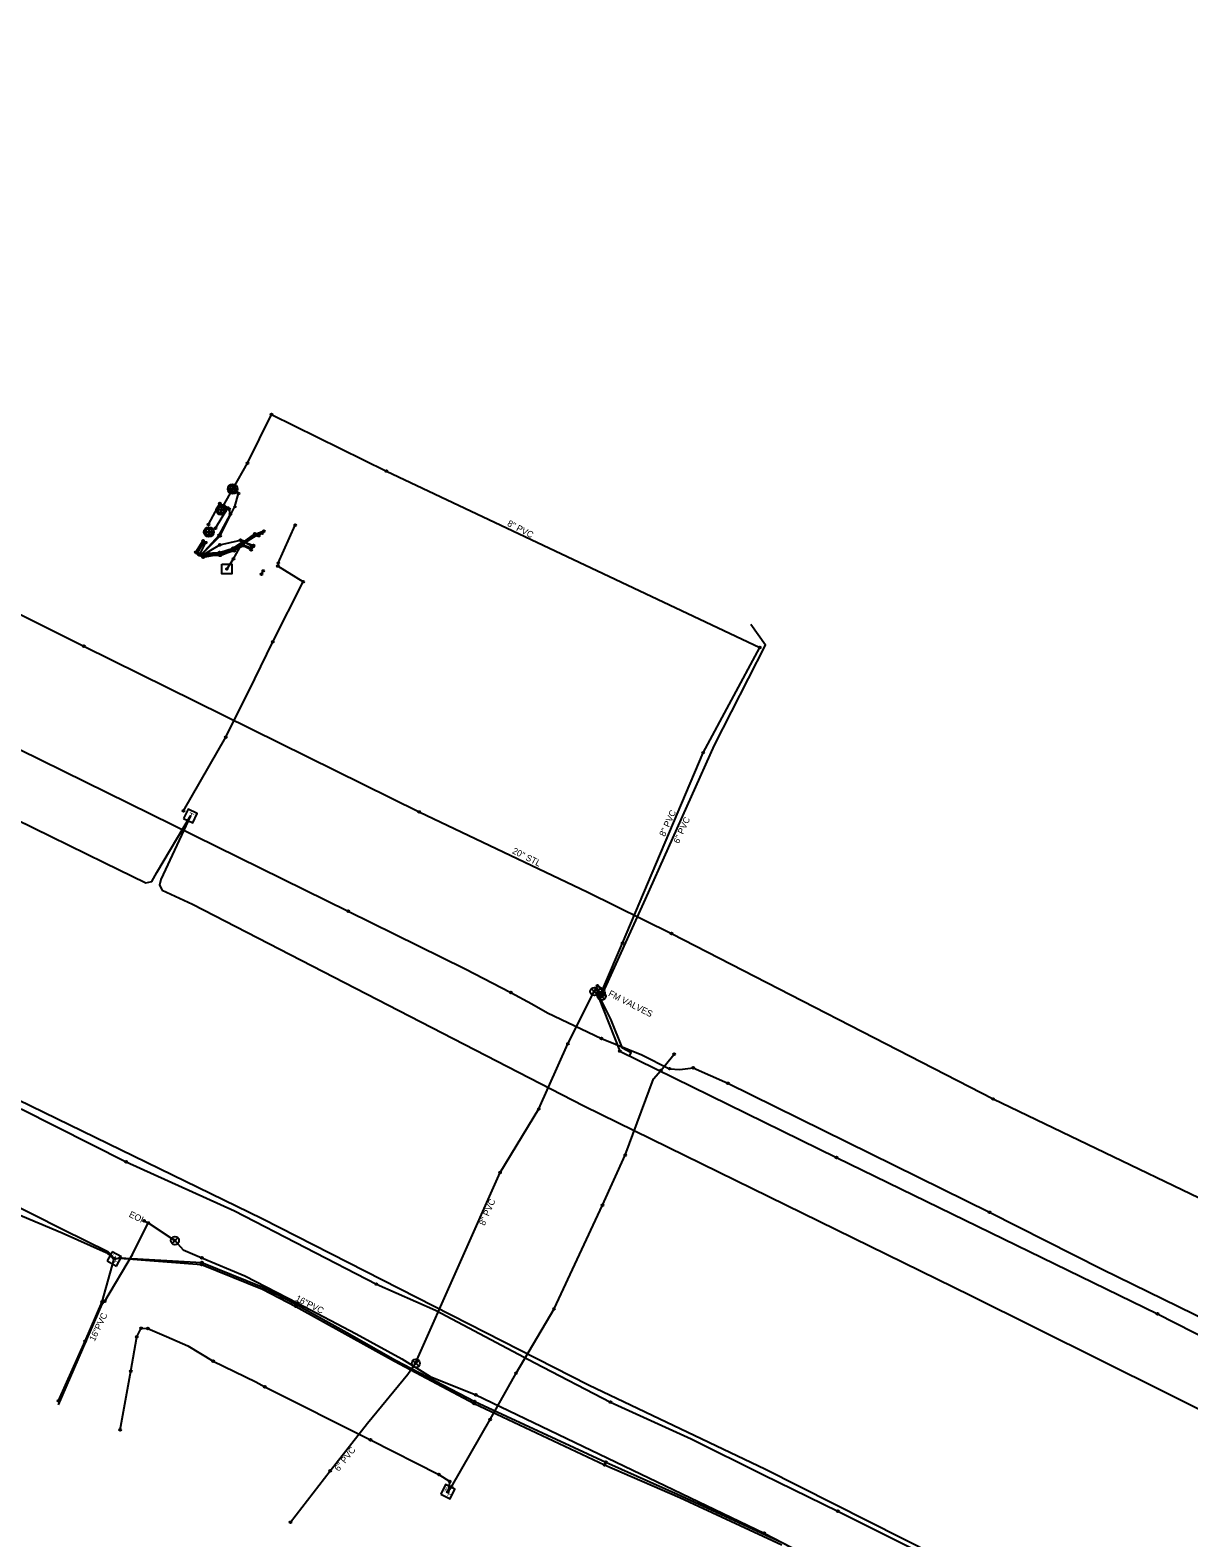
# Model space of a CAD drawing. Extents: x 2244485 to 2250986, y 199568 to 203007.
# Drawn here: x 2245302 to 2245934, y 202136 to 202958 of the extents above; entities that cross this region are included whole.
import ezdxf

# ---------------------------------------------------------------- set-up
doc = ezdxf.new("R2010")
doc.units = 0
for name, color, linetype in [('Default', 7, 'Continuous'), ('Exist Utilities Gas UG Line SUE LOS B', 7, 'Continuous'), ('Exist Utilities Gas UG Line SUE LOS B Text', 7, 'Continuous'), ('Exist Utilities Other Pole With Base CELL', 7, 'Continuous'), ('Exist Utilities Power UG Cable SUE LOS B', 7, 'Continuous'), ('Exist Utilities Sanitary Sewer Forced Main SUE LOS B', 7, 'Continuous'), ('Exist Utilities Sanitary Sewer Forced Main SUE LOS B Text', 7, 'Continuous'), ('Exist Utilities Sanitary Sewer Forced Main SUE LOS C', 7, 'Continuous'), ('Exist Utilities Sanitary Sewer Manhole CELL', 7, 'Continuous'), ('Exist Utilities Telephone Hand Hole CELL', 7, 'Continuous'), ('Exist Utilities Telephone Pedestal CELL', 7, 'Continuous'), ('Exist Utilities Telephone UG Cable SUE LOS C', 7, 'Continuous'), ('Exist Utilities Telephone UG FO SUE LOS B', 7, 'Continuous'), ('Exist Utilities Telephone UG FO SUE LOS C', 7, 'Continuous'), ('Exist Utilities TV Hand Hole CELL', 7, 'Continuous'), ('Exist Utilities TV UG FO Cable SUE LOS B', 7, 'Continuous'), ('Exist Utilities Water UG Line SUE LOS B', 7, 'Continuous'), ('Exist Utilities Water UG Line SUE LOS B Text', 7, 'Continuous'), ('Exist Utilities Water Valve CELL', 7, 'Continuous')]:
    doc.layers.add(name, color=color, linetype=linetype)

# ---------------------------------------------------------------- blocks, each defined once
blk = doc.blocks.new('SurveyPointCell')
at = {"layer": 'Default'}
for p, q in [((-0.5, 0), (0.5, 0)), ((0, -0.5), (0, 0.5))]:
    blk.add_line(p, q, dxfattribs=at)
blk.add_circle((0, 0), 0.5, dxfattribs=at)

msp = doc.modelspace()

# ---------------------------------------------------------------- linework, layer by layer
at = {"layer": 'Exist Utilities Gas UG Line SUE LOS B'}
msp.add_lwpolyline([(2244658.96, 202958.49), (2244721.96, 202928.3), (2244863.47, 202856.19), (2244912.51, 202831.57), (2245070.07, 202752.33), (2245256.14, 202659.91), (2245331.4, 202622.29), (2245514.38, 202531.76), (2245606.53, 202488.05), (2245652.12, 202465.42), (2245827.69, 202375.08), (2246001.01, 202291.84), (2246162.3, 202211.17), (2246329.12, 202125.74), (2246513.99, 202036.93), (2246642.7, 201974.75), (2246734.96, 201930.33), (2246858.92, 201868.26), (2246999.42, 201799.12), (2247177.53, 201710.71), (2247331.7, 201633.3), (2247466.92, 201567.22), (2247602.4, 201501.88), (2247749.1, 201426.01)], dxfattribs=at)
at = {"layer": 'Exist Utilities Other Pole With Base CELL'}
msp.add_line((2245409.46, 202664.37), (2245409.46, 202664.37), dxfattribs=at)
msp.add_lwpolyline([(2245406.73, 202667.07), (2245412.13, 202667.07), (2245412.13, 202661.67), (2245406.73, 202661.67), (2245406.73, 202667.07)], dxfattribs=at)
msp.add_circle((2245409.46, 202664.37), 0.0707, dxfattribs=at)
at = {"layer": 'Exist Utilities Power UG Cable SUE LOS B'}
for points in [[(2245395.21, 202671.86), (2245405.81, 202682.51), (2245413.9, 202698.4), (2245415.78, 202705.61)], [(2245395.33, 202671.83), (2245405.27, 202682.8), (2245411.37, 202694.33), (2245410.76, 202697.01)], [(2245437.55, 202667.62), (2245446.8, 202688.25)], [(2245392.56, 202673.48), (2245396.48, 202679.84)], [(2245396.95, 202679.11), (2245393.18, 202673.08)], [(2245393.77, 202672.75), (2245405.4, 202673.36), (2245412.94, 202675.71), (2245418.44, 202679.4), (2245424.01, 202677.24)], [(2245395.73, 202671.77), (2245405.63, 202677.57), (2245416.92, 202680.14), (2245423.82, 202676.57)], [(2245429.7, 202685.08), (2245424.88, 202683.28), (2245417.62, 202677.84), (2245413.1, 202675.46), (2245405.7, 202672.79), (2245396.4, 202671.15)], [(2245396.56, 202670.79), (2245405.7, 202672.45), (2245412.88, 202675.03), (2245417.7, 202677.69), (2245425.38, 202682.74), (2245428.75, 202683.95)], [(2245409.51, 202664.36), (2245413.06, 202669.87), (2245418, 202678.73), (2245424.77, 202683.65), (2245426.85, 202682.55)], [(2245422.72, 202674.83), (2245418.33, 202677.06), (2245413.53, 202674.26), (2245405.87, 202671.92), (2245394.27, 202672.11)], [(2245394.73, 202672.37), (2245397.93, 202678.77)], [(2245395.22, 202671.88), (2245405.74, 202671.81), (2245413.6, 202674.81), (2245418.32, 202677.62), (2245422.7, 202675.95)], [(2245385.83, 202532.39), (2245408.84, 202572.53), (2245424.65, 202604.36), (2245434.48, 202624.66), (2245451.18, 202657.41), (2245437.28, 202665.96)], [(2245428.32, 202661.55), (2245429.35, 202663.31)]]:
    msp.add_lwpolyline(points, dxfattribs=at)
at = {"layer": 'Exist Utilities Sanitary Sewer Forced Main SUE LOS B'}
for points in [[(2245399.42, 202688.67), (2245405.58, 202700.11), (2245407.65, 202699.04), (2245412.89, 202708.23), (2245420.72, 202722.07), (2245433.83, 202748.71), (2245496.51, 202717.84), (2245700.29, 202621.51)], [(2245403.32, 202686.64), (2245409.93, 202697.68), (2245407.63, 202698.99)], [(2245613.42, 202432.81), (2245614.64, 202435.08), (2245625.46, 202460.2), (2245669.41, 202564.11), (2245700.29, 202621.51)], [(2245512.48, 202230.83), (2245558.55, 202334.95), (2245579.66, 202369.62), (2245595.61, 202405.24), (2245610, 202433.72), (2245611.68, 202436.87), (2245614.64, 202435.08)], [(2245613.42, 202432.81), (2245612.33, 202430.62), (2245623.88, 202401.25), (2245742.14, 202343.1), (2245917.37, 202257.79), (2246026.41, 202202.34), (2246210.46, 202111.93), (2246345.24, 202046.28), (2246501.59, 201967.74), (2246585.87, 201926.12), (2246766.44, 201836.2), (2246874.3, 201784.12), (2246993.56, 201724.08), (2247186.6, 201626.85), (2247291.7, 201574.36), (2247419.93, 201509.91), (2247528.38, 201455.85), (2247631.36, 201405.97), (2247735.41, 201350.67), (2247801.59, 201317.51)], [(2245444.17, 202144.04), (2245465.88, 202172.11), (2245486.13, 202198.15), (2245508.27, 202224.8), (2245512.48, 202230.83)]]:
    msp.add_lwpolyline(points, dxfattribs=at)
at = {"layer": 'Exist Utilities Sanitary Sewer Forced Main SUE LOS C'}
msp.add_lwpolyline([(2245629.15, 202398.66), (2245630.09, 202400.26), (2245625.31, 202402.84), (2245619.07, 202418.57), (2245613.43, 202429.99), (2245613.98, 202431.19), (2245637.91, 202484.15), (2245675.61, 202568.28), (2245703.37, 202622.81), (2245695.34, 202634.02)], dxfattribs=at)
at = {"layer": 'Exist Utilities Sanitary Sewer Manhole CELL'}
for points in [[(2245412.59, 202709.74), (2245412.59, 202706.32), (2245412.59, 202708.03), (2245414.31, 202708.03), (2245410.88, 202708.03)], [(2245406.35, 202698.31), (2245406.35, 202694.88), (2245406.35, 202696.6), (2245408.06, 202696.6), (2245404.63, 202696.6)], [(2245399.64, 202686.24), (2245399.64, 202682.82), (2245399.64, 202684.53), (2245401.35, 202684.53), (2245397.93, 202684.53)]]:
    msp.add_lwpolyline(points, dxfattribs=at)
for centre, radius in [((2245412.59, 202708.03), 2.69), ((2245412.59, 202708.03), 1.71), ((2245406.35, 202696.6), 2.69), ((2245406.35, 202696.6), 1.71), ((2245399.64, 202684.53), 2.69), ((2245399.64, 202684.53), 1.71)]:
    msp.add_circle(centre, radius, dxfattribs=at)
at = {"layer": 'Exist Utilities Telephone Hand Hole CELL'}
for p, q in [((2245346.95, 202291.69), (2245344.18, 202286.68)), ((2245344.18, 202286.68), (2245349.19, 202283.91)), ((2245351.96, 202288.92), (2245346.95, 202291.69)), ((2245348.07, 202287.8), (2245348.07, 202287.8)), ((2245349.19, 202283.91), (2245351.96, 202288.92))]:
    msp.add_line(p, q, dxfattribs=at)
at = {"layer": 'Exist Utilities Telephone Pedestal CELL'}
msp.add_line((2245389.55, 202529.63), (2245389.55, 202529.63), dxfattribs=at)
msp.add_lwpolyline([(2245385.88, 202528.23), (2245390.95, 202525.86), (2245393.32, 202530.92), (2245388.26, 202533.3), (2245385.88, 202528.23)], dxfattribs=at)
at = {"layer": 'Exist Utilities Telephone UG Cable SUE LOS C'}
msp.add_lwpolyline([(2245130.24, 202608.24), (2245342.53, 202504.23), (2245365.2, 202493.05), (2245368.49, 202493.82), (2245371.26, 202498.68), (2245389.55, 202529.63), (2245373.43, 202494.83), (2245372.62, 202491.73), (2245374.18, 202489.1), (2245390.76, 202481.45), (2245604.3, 202371.42), (2245815.4, 202267.89), (2246098.91, 202126.77), (2246431.3, 201961.17), (2246435.26, 201960.69), (2246439.92, 201963.48), (2246448.75, 201975.62), (2246463.67, 201997.05), (2246446.22, 201961.62), (2246445.59, 201956.98), (2246446.26, 201954.54), (2246473.42, 201940.75), (2246700.68, 201828.04)], dxfattribs=at)
at = {"layer": 'Exist Utilities Telephone UG FO SUE LOS B'}
for points in [[(2244534.64, 202709.84), (2244609.27, 202669.97), (2244785.74, 202581.01), (2244840.19, 202553.14), (2244956.88, 202500.62), (2244986.55, 202486.03), (2245010.04, 202472.71), (2245040, 202457.4), (2245084.78, 202430.15), (2245170.23, 202380.19), (2245207.23, 202360.21), (2245246.97, 202340.05), (2245286.61, 202320.72), (2245320.18, 202303.77), (2245344.49, 202291.92), (2245347.99, 202287.98)], [(2245260.01, 202583.68), (2245475.72, 202477.57), (2245539.46, 202446.04), (2245564.49, 202433.2), (2245575.96, 202427.09), (2245584.49, 202422.12), (2245613.86, 202408.13), (2245635.9, 202399.1), (2245651.03, 202391.62), (2245656.6, 202391.2), (2245663.92, 202392.06), (2245682.86, 202383.66), (2245825.7, 202313.24), (2245887.18, 202282.16), (2245945.52, 202253.66), (2246007.29, 202222.98), (2246067.19, 202192.91), (2246123.94, 202164.93), (2246186.06, 202132.91)], [(2244991.72, 202447.43), (2244997.62, 202457.3), (2244999.68, 202459.77), (2245003.89, 202458.01), (2245037.21, 202441.81), (2245081.53, 202417.4), (2245166.02, 202372.45), (2245244.84, 202333.87), (2245285.27, 202316.42), (2245319.61, 202302.06), (2245343.58, 202291.26), (2245348.02, 202287.91)], [(2245297.18, 202369.62), (2245354.5, 202340.75), (2245413.57, 202314.06), (2245491.04, 202274.06), (2245523.39, 202259.78), (2245577.45, 202231.04), (2245618.81, 202209.65), (2245662.83, 202189.65), (2245702.29, 202169.93), (2245742.87, 202150.13), (2245837.39, 202103.05), (2245884.95, 202080.1), (2245941.39, 202052.03), (2246102.15, 201972.13), (2246160.8, 201943.07), (2246225.68, 201910.57), (2246354.46, 201846.2), (2246394.94, 201822.07), (2246546.85, 201748.25)], [(2245317.61, 202210.29), (2245332.09, 202242.94), (2245341.42, 202264.38), (2245347.93, 202287.91)], [(2245348.07, 202287.8), (2245351.12, 202288.29), (2245395.88, 202285.86), (2245429.04, 202272.44), (2245447.42, 202262.89), (2245475.01, 202247.57), (2245501.44, 202232.58), (2245544.7, 202210.01), (2245616.26, 202176.91), (2245657.32, 202158.54), (2245712.97, 202132.89), (2245773.8, 202098.67), (2245830.52, 202069.53), (2245875.55, 202047.04), (2245967.13, 202002.37), (2246055.75, 201957.91), (2246176.16, 201896.67), (2246250.38, 201859.8), (2246334.37, 201818.25), (2246368.32, 201799.38), (2246371.55, 201797.86)], [(2245348.07, 202287.8), (2245351.13, 202288.21), (2245395.61, 202284.75), (2245428.9, 202271.31), (2245447.19, 202261.86), (2245500.88, 202231.94), (2245544.46, 202208.81), (2245615.61, 202175.36), (2245656.7, 202157.5), (2245712.28, 202131.67)]]:
    msp.add_lwpolyline(points, dxfattribs=at)
at = {"layer": 'Exist Utilities Telephone UG FO SUE LOS C'}
msp.add_lwpolyline([(2244555.09, 202740.38), (2244612.45, 202712.07), (2244680.5, 202678.83), (2244750.01, 202644.92), (2244809.78, 202614.66), (2244896.14, 202572.42), (2244969.14, 202536), (2245027.26, 202506.94), (2245218.26, 202412.25), (2245428.66, 202309.78), (2245606.8, 202219.11), (2245703.35, 202173.01), (2245852.59, 202097.7), (2245983.22, 202033.13), (2246107.4, 201971.58), (2246219.73, 201915.39), (2246355.16, 201847.48), (2246395.74, 201823.66), (2246448.95, 201797.92), (2246548.24, 201751.03)], dxfattribs=at)
at = {"layer": 'Exist Utilities TV Hand Hole CELL'}
msp.add_line((2245530.06, 202160.76), (2245530.06, 202160.76), dxfattribs=at)
msp.add_lwpolyline([(2245526.21, 202159.46), (2245531.36, 202156.91), (2245533.91, 202162.06), (2245528.76, 202164.61), (2245526.21, 202159.46)], dxfattribs=at)
at = {"layer": 'Exist Utilities TV UG FO Cable SUE LOS B'}
msp.add_lwpolyline([(2245351.21, 202194.41), (2245357.04, 202226.58), (2245360.28, 202245.31), (2245362.68, 202249.91), (2245366.35, 202249.79), (2245376.5, 202245.43), (2245388.24, 202240.37), (2245402.01, 202231.99), (2245425.26, 202220.72), (2245430.16, 202217.96), (2245487.84, 202189), (2245525.23, 202170.15), (2245531.08, 202166.34), (2245530.01, 202160.61), (2245532.12, 202163.34), (2245553.14, 202200.08), (2245567.26, 202225.44), (2245588, 202260.58), (2245614.46, 202317.14), (2245626.91, 202344.47), (2245642.21, 202386.12), (2245646.33, 202390.64), (2245653.56, 202399.57)], dxfattribs=at)
at = {"layer": 'Exist Utilities Water UG Line SUE LOS B'}
for points in [[(2245317.6, 202208.11), (2245341.46, 202263.05), (2245342.85, 202264.7), (2245357.99, 202290.22), (2245366.59, 202307.41)], [(2245364.27, 202308.61), (2245366.59, 202307.41), (2245381, 202297.8), (2245385.67, 202292.83), (2245395.79, 202288.35), (2245419.32, 202278.5), (2245448.28, 202263.59), (2245479.99, 202246.8), (2245504.9, 202233.28), (2245520.47, 202223.52), (2245545.35, 202213.61), (2245702.65, 202138.15), (2245808.82, 202083.18), (2245963.17, 202009.49), (2246100.08, 201939.27), (2246176.18, 201901.25), (2246305.63, 201836.71), (2246381.12, 201802.25)]]:
    msp.add_lwpolyline(points, dxfattribs=at)
at = {"layer": 'Exist Utilities Water Valve CELL'}
for points in [[(2245611.58, 202435.29), (2245608.43, 202432.15), (2245610.01, 202433.72), (2245611.58, 202432.15), (2245608.43, 202435.29)], [(2245615.11, 202434.58), (2245611.96, 202431.43), (2245613.53, 202433.01), (2245615.11, 202431.43), (2245611.96, 202434.58)], [(2245615.55, 202432.76), (2245612.4, 202429.61), (2245613.98, 202431.19), (2245615.55, 202429.61), (2245612.4, 202432.76)], [(2245382.69, 202299.36), (2245379.54, 202296.21), (2245381.11, 202297.79), (2245382.69, 202296.21), (2245379.54, 202299.36)], [(2245514.17, 202232.38), (2245511.02, 202229.23), (2245512.59, 202230.81), (2245514.17, 202229.23), (2245511.02, 202232.38)]]:
    msp.add_lwpolyline(points, dxfattribs=at)
for centre in [(2245610.01, 202433.72), (2245613.53, 202433.01), (2245613.98, 202431.19), (2245381.11, 202297.79), (2245512.59, 202230.81)]:
    msp.add_circle(centre, 2.23, dxfattribs=at)

# ---------------------------------------------------------------- block references
at = {"layer": 'Default'}
for p in [(2245433.83, 202748.71), (2245420.72, 202722.07), (2245496.51, 202717.84), (2245412.89, 202708.23), (2245415.78, 202705.61), (2245405.58, 202700.11), (2245407.63, 202698.99), (2245407.65, 202699.04), (2245409.93, 202697.68), (2245410.76, 202697.01), (2245413.9, 202698.4), (2245399.42, 202688.67), (2245411.37, 202694.33), (2245446.8, 202688.25), (2245396.48, 202679.84), (2245396.95, 202679.11), (2245397.93, 202678.77), (2245403.32, 202686.64), (2245405.27, 202682.8), (2245405.81, 202682.51), (2245416.92, 202680.14), (2245418, 202678.73), (2245418.44, 202679.4), (2245424.77, 202683.65), (2245424.88, 202683.28), (2245425.38, 202682.74), (2245426.85, 202682.55), (2245428.75, 202683.95), (2245429.7, 202685.08), (2245392.56, 202673.48), (2245393.18, 202673.08), (2245393.77, 202672.75), (2245394.27, 202672.11), (2245394.73, 202672.37), (2245395.21, 202671.86), (2245395.22, 202671.88), (2245395.33, 202671.83), (2245395.73, 202671.77), (2245396.4, 202671.15), (2245396.56, 202670.79), (2245405.4, 202673.36), (2245405.63, 202677.57), (2245405.7, 202672.79), (2245405.7, 202672.45), (2245405.74, 202671.81), (2245405.87, 202671.92), (2245412.88, 202675.03), (2245412.94, 202675.71), (2245413.1, 202675.46), (2245413.53, 202674.26), (2245413.6, 202674.81), (2245417.62, 202677.84), (2245417.7, 202677.69), (2245418.32, 202677.62), (2245418.33, 202677.06), (2245422.7, 202675.95), (2245422.72, 202674.83), (2245423.82, 202676.57), (2245424.01, 202677.24), (2245409.51, 202664.36), (2245413.06, 202669.87), (2245429.35, 202663.31), (2245437.28, 202665.96), (2245437.55, 202667.62), (2245428.32, 202661.55), (2245451.18, 202657.41), (2245331.4, 202622.29), (2245434.48, 202624.66), (2245700.29, 202621.51), (2245408.84, 202572.53), (2245669.41, 202564.11), (2245385.83, 202532.39), (2245514.38, 202531.76), (2245475.72, 202477.57), (2245652.12, 202465.42), (2245625.46, 202460.2), (2245564.49, 202433.2), (2245610, 202433.72), (2245611.68, 202436.87), (2245613.42, 202432.81), (2245613.42, 202432.81), (2245614.64, 202435.08), (2245614.64, 202435.08), (2245612.33, 202430.62), (2245613.98, 202431.19), (2245613.86, 202408.13), (2245595.61, 202405.24), (2245623.88, 202401.25), (2245653.56, 202399.57), (2245646.33, 202390.64), (2245651.03, 202391.62), (2245663.92, 202392.06), (2245682.86, 202383.66), (2245827.69, 202375.08), (2245579.66, 202369.62), (2245626.91, 202344.47), (2245742.14, 202343.1), (2245354.5, 202340.75), (2245558.55, 202334.95), (2245614.46, 202317.14), (2245364.27, 202308.61), (2245825.7, 202313.24), (2245366.59, 202307.41), (2245366.59, 202307.41), (2245381, 202297.8), (2245347.93, 202287.91), (2245347.99, 202287.98), (2245348.02, 202287.91), (2245351.12, 202288.29), (2245351.13, 202288.21), (2245395.61, 202284.75), (2245395.79, 202288.35), (2245395.88, 202285.86), (2245491.04, 202274.06), (2245341.42, 202264.38), (2245342.85, 202264.7), (2245447.19, 202261.86), (2245447.42, 202262.89), (2245448.28, 202263.59), (2245588, 202260.58), (2245917.37, 202257.79), (2245332.09, 202242.94), (2245360.28, 202245.31), (2245362.68, 202249.91), (2245366.35, 202249.79), (2245357.04, 202226.58), (2245402.01, 202231.99), (2245512.48, 202230.83), (2245430.16, 202217.96), (2245567.26, 202225.44), (2245317.61, 202210.29), (2245544.7, 202210.01), (2245545.35, 202213.61), (2245618.81, 202209.65), (2245544.46, 202208.81), (2245351.21, 202194.41), (2245553.14, 202200.08), (2245487.84, 202189), (2245616.26, 202176.91), (2245465.88, 202172.11), (2245525.23, 202170.15), (2245615.61, 202175.36), (2245530.01, 202160.61), (2245531.08, 202166.34), (2245532.12, 202163.34), (2245444.17, 202144.04), (2245742.87, 202150.13), (2245702.65, 202138.15)]:
    msp.add_blockref('SurveyPointCell', p, dxfattribs=at)

# ---------------------------------------------------------------- texts
at = {"layer": 'Exist Utilities Gas UG Line SUE LOS B Text'}
msp.add_text('20" STL', height=3.5, rotation=333.09153, dxfattribs=at).set_placement((2245564.89, 202509.39))
at = {"layer": 'Exist Utilities Sanitary Sewer Forced Main SUE LOS B'}
msp.add_text('FM VALVES', height=3.5, rotation=333.09153, dxfattribs=at).set_placement((2245617.29, 202431.53))
at = {"layer": 'Exist Utilities Sanitary Sewer Forced Main SUE LOS B Text'}
for s, rotation, p in [('8" PVC', 332.41532, (2245562.15, 202688.17)), ('8" PVC', 65.43585, (2245648.46, 202518.02)), ('6" PVC', 65.60363, (2245656.14, 202514.19)), ('8" PVC', 66.79986, (2245550.15, 202305.68)), ('6" PVC', 51.68752, (2245470.53, 202171.54))]:
    msp.add_text(s, height=3.5, rotation=rotation, dxfattribs=at).set_placement(p)
at = {"layer": 'Exist Utilities Telephone Hand Hole CELL'}
for p in [(2245345.96, 202288.29), (2245347.5, 202285.76)]:
    msp.add_text('H', height=2.5, rotation=331.07712, dxfattribs=at).set_placement(p)
at = {"layer": 'Exist Utilities Telephone Pedestal CELL'}
msp.add_text('T', height=3.42, rotation=334.87134, dxfattribs=at).set_placement((2245387.8, 202528.56))
at = {"layer": 'Exist Utilities TV Hand Hole CELL'}
for p in [(2245527.9, 202161.1), (2245529.56, 202158.65)]:
    msp.add_text('H', height=2.5, rotation=333.68902, dxfattribs=at).set_placement(p)
at = {"layer": 'Exist Utilities Water UG Line SUE LOS B'}
msp.add_text('EOI', height=3.5, rotation=334.3343, dxfattribs=at).set_placement((2245355.68, 202310.91))
at = {"layer": 'Exist Utilities Water UG Line SUE LOS B Text'}
for rotation, p in [(333.09153, (2245446.54, 202265.13)), (64.37325, (2245337.3, 202242.51))]:
    msp.add_text('16"PVC', height=3.5, rotation=rotation, dxfattribs=at).set_placement(p)

doc.saveas('drawing.dxf')
